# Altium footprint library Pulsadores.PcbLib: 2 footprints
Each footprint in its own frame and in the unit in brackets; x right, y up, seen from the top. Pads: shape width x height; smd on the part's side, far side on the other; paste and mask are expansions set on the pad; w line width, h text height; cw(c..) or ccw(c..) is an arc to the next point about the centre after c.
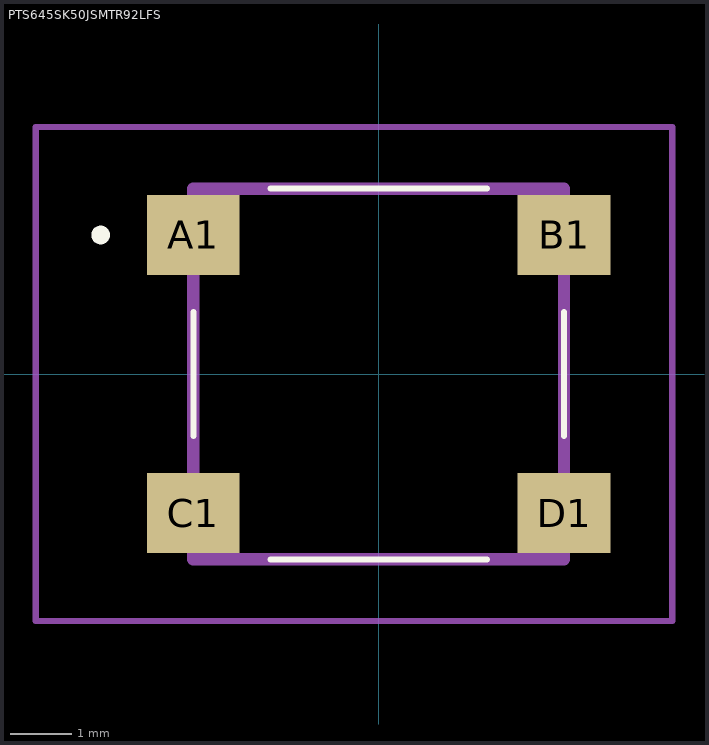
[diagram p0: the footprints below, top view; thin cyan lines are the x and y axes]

## PCBComponent_1 [mm]

## PTS645SK50JSMTR92LFS [mm]
pads (4):
  rect 1.5x1.3 smd: A1(-3,2.25) B1(3,2.25) C1(-3,-2.25) D1(3,-2.25)
Top Overlay:
  lines w0.1: -3,-1 -3,1 -3,-1 ; -1.75,-3 1.75,-3 -1.75,-3 ; -1.75,3 1.75,3 -1.75,3 ; 3,-1 3,1 3,-1
  lines w0.2: -4.5,2.2 cw(c-4.5,2.25) -4.5,2.3 ; -4.5,2.2 ccw(c-4.5,2.25) -4.5,2.3 ; -4.5,2.2 cw(c-4.5,2.25) -4.5,2.3
Mechanical 13:
  lines w0.2: -3,-3 -3,3 3,3 3,-3 -3,-3
Mechanical 15:
  lines w0.1: -5.55,-4 -5.55,4 4.75,4 4.75,-4 -5.55,-4
3D body "PTS645SK50JSMTR92_LFS.stp": height 4.84, standoff 0, extent -3.24,-3 3.44,3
